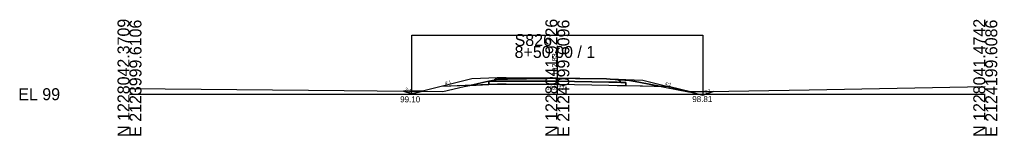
# Model space of a CAD drawing. Extents: x 2118382 to 2118616, y 1213030 to 1222057.
# Drawn here: x 2118381.9 to 2118610.4, y 1219030.1 to 1219057.3 of the extents above; entities that cross this region are included whole.
import ezdxf

# ---------------------------------------------------------------- set-up
doc = ezdxf.new("R2010")
doc.units = 0
for name, color, linetype in [('XS_CELL', 7, 'Continuous'), ('XS_M_DITCH', 7, 'Continuous'), ('XS_M_SHAPES_EARTHWORK', 7, 'Continuous'), ('XS_P_FINISHED_GRADE', 7, 'Continuous'), ('XS_P_FINISHED_GRADE_ELEV_TX', 7, 'Continuous'), ('XS_P_SUBGRADE_GRANULAR', 7, 'Continuous'), ('XS_P_SUBGRADE_PAVEMENT', 7, 'Continuous'), ('XS_P_TX_DCH', 7, 'Continuous'), ('XS_P_TX_FS_BS', 7, 'Continuous'), ('XS_X_GROUND', 7, 'Continuous'), ('XS_X_GROUND_TX', 7, 'Continuous')]:
    doc.layers.add(name, color=color, linetype=linetype)

msp = doc.modelspace()

# ---------------------------------------------------------------- linework, layer by layer
at = {"layer": 'XS_CELL'}
for p, q in [((2118507.6, 1219039.8), (2118507.6, 1219051.11)), ((2118407.6, 1219039.8), (2118507.6, 1219039.8)), ((2118507.6, 1219039.8), (2118607.6, 1219039.8))]:
    msp.add_line(p, q, dxfattribs=at)
at = {"layer": 'XS_M_DITCH'}
for p, q in [((2118473.6, 1219039.9), (2118473.6, 1219053.63)), ((2118473.6, 1219053.63), (2118541.6, 1219053.63)), ((2118541.6, 1219053.63), (2118541.6, 1219039.61))]:
    msp.add_line(p, q, dxfattribs=at)
at = {"layer": 'XS_M_SHAPES_EARTHWORK'}
for p, q in [((2118493.69, 1219043.3), (2118492.87, 1219043.12)), ((2118494.86, 1219043.3), (2118493.69, 1219043.3)), ((2118495.93, 1219043.34), (2118494.86, 1219043.3)), ((2118504.82, 1219043.51), (2118495.93, 1219043.34)), ((2118507.6, 1219043.57), (2118504.82, 1219043.51)), ((2118511.8, 1219043.5), (2118507.6, 1219043.57)), ((2118512.81, 1219043.48), (2118511.8, 1219043.5)), ((2118519.09, 1219043.37), (2118512.81, 1219043.48)), ((2118519.94, 1219043.33), (2118519.09, 1219043.37)), ((2118521.8, 1219043.22), (2118519.94, 1219043.33)), ((2118524.46, 1219043.05), (2118521.8, 1219043.22)), ((2118521.8, 1219043.22), (2118522.28, 1219042.88)), ((2118522.28, 1219042.88), (2118521.8, 1219043.22)), ((2118480.46, 1219041.61), (2118476.04, 1219040.51)), ((2118487.13, 1219041.88), (2118480.46, 1219041.61)), ((2118480.85, 1219040.46), (2118485.83, 1219041.6)), ((2118485.83, 1219041.6), (2118487.13, 1219041.88)), ((2118491.6, 1219042.85), (2118487.13, 1219041.88)), ((2118487.13, 1219041.88), (2118491.6, 1219042.06)), ((2118492.87, 1219043.12), (2118491.6, 1219042.85)), ((2118492.87, 1219043.12), (2118491.6, 1219042.85)), ((2118492.74, 1219042.89), (2118491.6, 1219042.85)), ((2118491.6, 1219042.85), (2118492.74, 1219042.89)), ((2118491.6, 1219042.85), (2118492.74, 1219042.89)), ((2118491.6, 1219042.85), (2118491.6, 1219042.06)), ((2118491.6, 1219042.06), (2118491.6, 1219042.85)), ((2118491.6, 1219042.06), (2118493.6, 1219042.14)), ((2118492.87, 1219043.12), (2118492.74, 1219042.89)), ((2118492.74, 1219042.89), (2118492.87, 1219043.12)), ((2118492.74, 1219042.89), (2118492.87, 1219043.12)), ((2118492.74, 1219042.89), (2118495.6, 1219042.89)), ((2118495.6, 1219042.89), (2118492.74, 1219042.89)), ((2118493.6, 1219042.14), (2118495.6, 1219042.14)), ((2118495.6, 1219042.89), (2118507.6, 1219042.88)), ((2118507.6, 1219042.88), (2118495.6, 1219042.89)), ((2118495.6, 1219042.14), (2118507.6, 1219042.13)), ((2118507.6, 1219042.88), (2118519.6, 1219042.64)), ((2118519.6, 1219042.64), (2118507.6, 1219042.88)), ((2118507.6, 1219042.13), (2118519.6, 1219041.89)), ((2118519.6, 1219042.64), (2118521.6, 1219042.6)), ((2118521.6, 1219042.6), (2118519.6, 1219042.64)), ((2118519.6, 1219041.89), (2118521.6, 1219041.85)), ((2118521.6, 1219042.6), (2118522.46, 1219042.57)), ((2118522.46, 1219042.57), (2118521.6, 1219042.6)), ((2118521.6, 1219041.85), (2118523.6, 1219041.81)), ((2118522.28, 1219042.88), (2118522.46, 1219042.57)), ((2118522.46, 1219042.57), (2118522.28, 1219042.88)), ((2118522.46, 1219042.57), (2118523.6, 1219042.52)), ((2118523.6, 1219042.52), (2118522.46, 1219042.57)), ((2118523.6, 1219042.52), (2118523.6, 1219041.81)), ((2118523.6, 1219041.81), (2118523.6, 1219042.52)), ((2118523.6, 1219041.81), (2118531.47, 1219041.66)), ((2118526.63, 1219042.61), (2118524.46, 1219043.05)), ((2118531.47, 1219041.66), (2118526.63, 1219042.61)), ((2118533.6, 1219041.61), (2118531.47, 1219041.66)), ((2118531.47, 1219041.66), (2118538.22, 1219040.32)), ((2118538.72, 1219040.33), (2118533.6, 1219041.61)), ((2118471.65, 1219040.55), (2118473.6, 1219039.9)), ((2118476.04, 1219040.51), (2118471.65, 1219040.55)), ((2118473.6, 1219039.9), (2118476.04, 1219040.51)), ((2118476.04, 1219040.51), (2118480.85, 1219040.46)), ((2118538.22, 1219040.32), (2118538.72, 1219040.33)), ((2118544.03, 1219040.42), (2118538.72, 1219040.33)), ((2118538.72, 1219040.33), (2118541.6, 1219039.61)), ((2118541.6, 1219039.61), (2118544.03, 1219040.42))]:
    msp.add_line(p, q, dxfattribs=at)
msp.add_lwpolyline([(2118491.6, 1219042.85), (2118491.6, 1219042.85)], dxfattribs=at)
msp.add_lwpolyline([(2118491.6, 1219042.85), (2118491.6, 1219042.85)], dxfattribs=at)
at = {"layer": 'XS_P_FINISHED_GRADE'}
for p, q in [((2118487.6, 1219043.4), (2118473.6, 1219039.9)), ((2118493.6, 1219043.64), (2118487.6, 1219043.4)), ((2118495.6, 1219043.64), (2118493.6, 1219043.64)), ((2118495.6, 1219043.64), (2118507.6, 1219043.63)), ((2118507.6, 1219043.63), (2118519.6, 1219043.39)), ((2118519.6, 1219043.39), (2118521.6, 1219043.35)), ((2118521.6, 1219043.35), (2118527.6, 1219043.11)), ((2118527.6, 1219043.11), (2118541.6, 1219039.61)), ((2118473.6, 1219039.9), (2118471.65, 1219040.55)), ((2118541.6, 1219039.61), (2118544.03, 1219040.42))]:
    msp.add_line(p, q, dxfattribs=at)
at = {"layer": 'XS_P_SUBGRADE_GRANULAR'}
for p, q in [((2118491.6, 1219042.06), (2118480.46, 1219041.61)), ((2118492.74, 1219042.89), (2118491.6, 1219042.85)), ((2118491.6, 1219042.06), (2118491.6, 1219042.85)), ((2118493.6, 1219042.14), (2118491.6, 1219042.06)), ((2118495.6, 1219042.14), (2118493.6, 1219042.14)), ((2118495.6, 1219042.14), (2118507.6, 1219042.13)), ((2118507.6, 1219042.13), (2118519.6, 1219041.89)), ((2118519.6, 1219041.89), (2118521.6, 1219041.85)), ((2118521.6, 1219041.85), (2118523.6, 1219041.81)), ((2118521.6, 1219041.85), (2118523.6, 1219041.81)), ((2118522.46, 1219042.57), (2118523.6, 1219042.52)), ((2118523.6, 1219041.81), (2118523.6, 1219042.52)), ((2118523.6, 1219041.81), (2118533.6, 1219041.61))]:
    msp.add_line(p, q, dxfattribs=at)
at = {"layer": 'XS_P_SUBGRADE_PAVEMENT'}
for p, q in [((2118492.91, 1219043.18), (2118492.74, 1219042.89)), ((2118493.6, 1219043.64), (2118492.91, 1219043.18)), ((2118521.6, 1219043.35), (2118522.28, 1219042.88)), ((2118495.6, 1219042.89), (2118492.74, 1219042.89)), ((2118495.6, 1219042.89), (2118507.6, 1219042.88)), ((2118507.6, 1219042.88), (2118519.6, 1219042.64)), ((2118519.6, 1219042.64), (2118521.6, 1219042.6)), ((2118521.6, 1219042.6), (2118522.46, 1219042.57)), ((2118522.28, 1219042.88), (2118522.46, 1219042.57))]:
    msp.add_line(p, q, dxfattribs=at)
at = {"layer": 'XS_X_GROUND'}
for p, q in [((2118485.83, 1219041.6), (2118493.69, 1219043.3)), ((2118493.69, 1219043.3), (2118494.86, 1219043.3)), ((2118494.86, 1219043.3), (2118495.93, 1219043.34)), ((2118495.93, 1219043.34), (2118504.82, 1219043.51)), ((2118504.82, 1219043.51), (2118507.6, 1219043.57)), ((2118507.6, 1219043.57), (2118507.6, 1219043.57)), ((2118507.6, 1219043.57), (2118511.8, 1219043.5)), ((2118511.8, 1219043.5), (2118512.81, 1219043.48)), ((2118512.81, 1219043.48), (2118519.09, 1219043.37)), ((2118519.09, 1219043.37), (2118519.94, 1219043.33)), ((2118519.94, 1219043.33), (2118524.46, 1219043.05)), ((2118407.6, 1219041.14), (2118457.78, 1219040.68)), ((2118480.85, 1219040.46), (2118485.83, 1219041.6)), ((2118524.46, 1219043.05), (2118526.63, 1219042.61)), ((2118526.63, 1219042.61), (2118538.22, 1219040.32)), ((2118566.43, 1219040.8), (2118607.6, 1219041.6)), ((2118457.78, 1219040.68), (2118480.85, 1219040.46)), ((2118538.22, 1219040.32), (2118566.43, 1219040.8))]:
    msp.add_line(p, q, dxfattribs=at)

# ---------------------------------------------------------------- texts
at = {"layer": 'XS_CELL'}
for s, p in [('N 1228042.3709', (2118407.6, 1219029.8)), ('E 2123999.6106', (2118410.4, 1219029.8)), ('N 1228041.9226', (2118507.6, 1219029.8)), ('E 2124099.6096', (2118510.4, 1219029.8)), ('N 1228041.4742', (2118607.6, 1219029.8)), ('E 2124199.6086', (2118610.4, 1219029.8))]:
    msp.add_text(s, height=2.8, rotation=90, dxfattribs=at).set_placement(p)
for s, p in [('S826', (2118497.6, 1219051.11)), ('8+50.00 / 1', (2118497.6, 1219048.31)), ('EL 99', (2118381.6, 1219038.4))]:
    msp.add_text(s, height=2.8, dxfattribs=at).set_placement(p)
at = {"layer": 'XS_P_FINISHED_GRADE_ELEV_TX'}
msp.add_text(' 102.83', height=1.25, rotation=90, dxfattribs=at).set_placement((2118507.6, 1219043.63))
at = {"layer": 'XS_P_TX_DCH'}
for s, p in [('99.10', (2118470.86, 1219037.9)), ('98.81', (2118539.12, 1219037.95))]:
    msp.add_text(s, height=1.4, dxfattribs=at).set_placement(p)
at = {"layer": 'XS_P_TX_FS_BS'}
for s, rotation, p in [('3:1', 341.5651, (2118471.9, 1219040.64)), ('4:1', 14.0362, (2118481.39, 1219041.94)), ('4:1', 345.9638, (2118532.65, 1219041.99)), ('3:1', 18.4349, (2118542.14, 1219039.9))]:
    msp.add_text(s, height=0.8, rotation=rotation, dxfattribs=at).set_placement(p)
at = {"layer": 'XS_X_GROUND_TX'}
msp.add_text('102.77', height=1, dxfattribs=at).set_placement((2118505.05, 1219040.78))

doc.saveas('drawing.dxf')
